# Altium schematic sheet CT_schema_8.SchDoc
size 277 x 170 mm
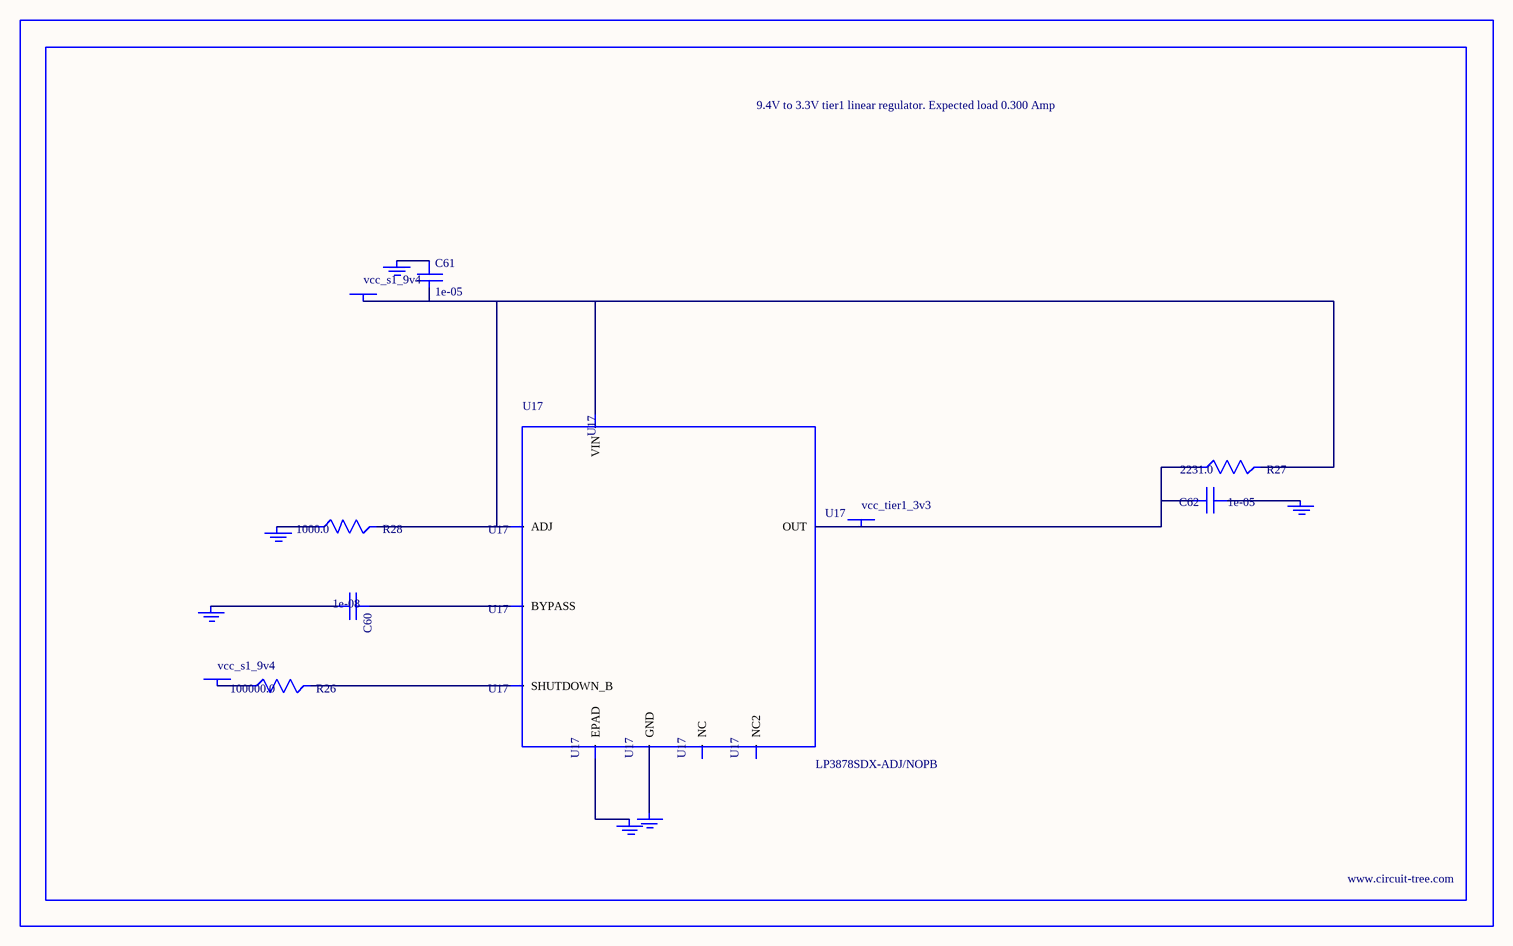
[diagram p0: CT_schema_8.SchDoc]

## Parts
BORDER7  (no value)
C60  1e-08  [C0402]
C61  1e-05  [C1206]
C62  1e-05  [C1210]
GND_INSTANCE_7_0  (no value)
GND_INSTANCE_7_1  (no value)
GND_INSTANCE_7_2  (no value)
GND_INSTANCE_7_3  (no value)
GND_INSTANCE_7_4  (no value)
GND_INSTANCE_7_5  (no value)
POWER_INSTANCE_7_0  vcc_s1_9v4
POWER_INSTANCE_7_1  vcc_s1_9v4
POWER_INSTANCE_7_2  vcc_tier1_3v3
R26  100000.0  [R0603]
R27  2231.0  [R0603]
R28  1000.0  [R0603]
U17  LP3878SDX-ADJ/NOPB  [WSON-8]

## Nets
NetC60_1: C60.1 U17.1(BYPASS)
NetC60_2: C60.2 GND_INSTANCE_7_0.0(GND)
NetC61_1: C61.1 GND_INSTANCE_7_1.0(GND)
NetC61_2: C61.2 POWER_INSTANCE_7_0.0(PWR) R27.2 R28.2 U17.4(VIN) U17.6(ADJ)
NetC62_1: C62.1 GND_INSTANCE_7_2.0(GND)
NetC62_2: C62.2 POWER_INSTANCE_7_2.0(PWR) R27.1 U17.5(OUT)
NetGND_INSTANCE_7_3_0: GND_INSTANCE_7_3.0(GND) R28.1
NetGND_INSTANCE_7_4_0: GND_INSTANCE_7_4.0(GND) U17.PAD(EPAD)
NetGND_INSTANCE_7_5_0: GND_INSTANCE_7_5.0(GND) U17.3(GND)
NetPOWER_INSTANCE_7_1_0: POWER_INSTANCE_7_1.0(PWR) R26.1
NetR26_2: R26.2 U17.8(SHUTDOWN_B)

Not connected (* = marked no-connect by the designer): U17 2(NC) 7(NC2)

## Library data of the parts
BORDER7 = BORDER_PAGE7
C60 = C0402C103K3RAC
C61 = C1206C106K3RACTU
C62 = GRM32DR61E106MA12L
GND_INSTANCE_7_0-GND_INSTANCE_7_5 = GND
POWER_INSTANCE_7_0-POWER_INSTANCE_7_2 = PWR
R26 = RC0603JR-07100KL
R27 = R27
R28 = RC0603JR-071KL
